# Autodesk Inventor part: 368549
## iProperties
Created: 2006-07
Part Number: 368549
Material: A2
Description: Scheibe
Vendor: Autodesk Inc.
Document SubType Name: Modeling
Standard: DIN 9021
Designer: I.Baliuc
Standards Organization: DIN
Language: de-DE
Size Designation: 6.4
Categories: <MemberInstance Version="R10.0.0"><Categories><Category DisplayName="Schrauben" InternalName="e4da775c-781d-43d5-af7c-5136215cf5a6" Mnemonic="FSTN"><Category Di
Density: 8.08 g/cm^3
Abmessung: 6.4
Author: T.Messerschmitt
Comments: DIN 9021 - 6.4
Revision Number: 368549
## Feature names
1. Körper [Extrusion]
